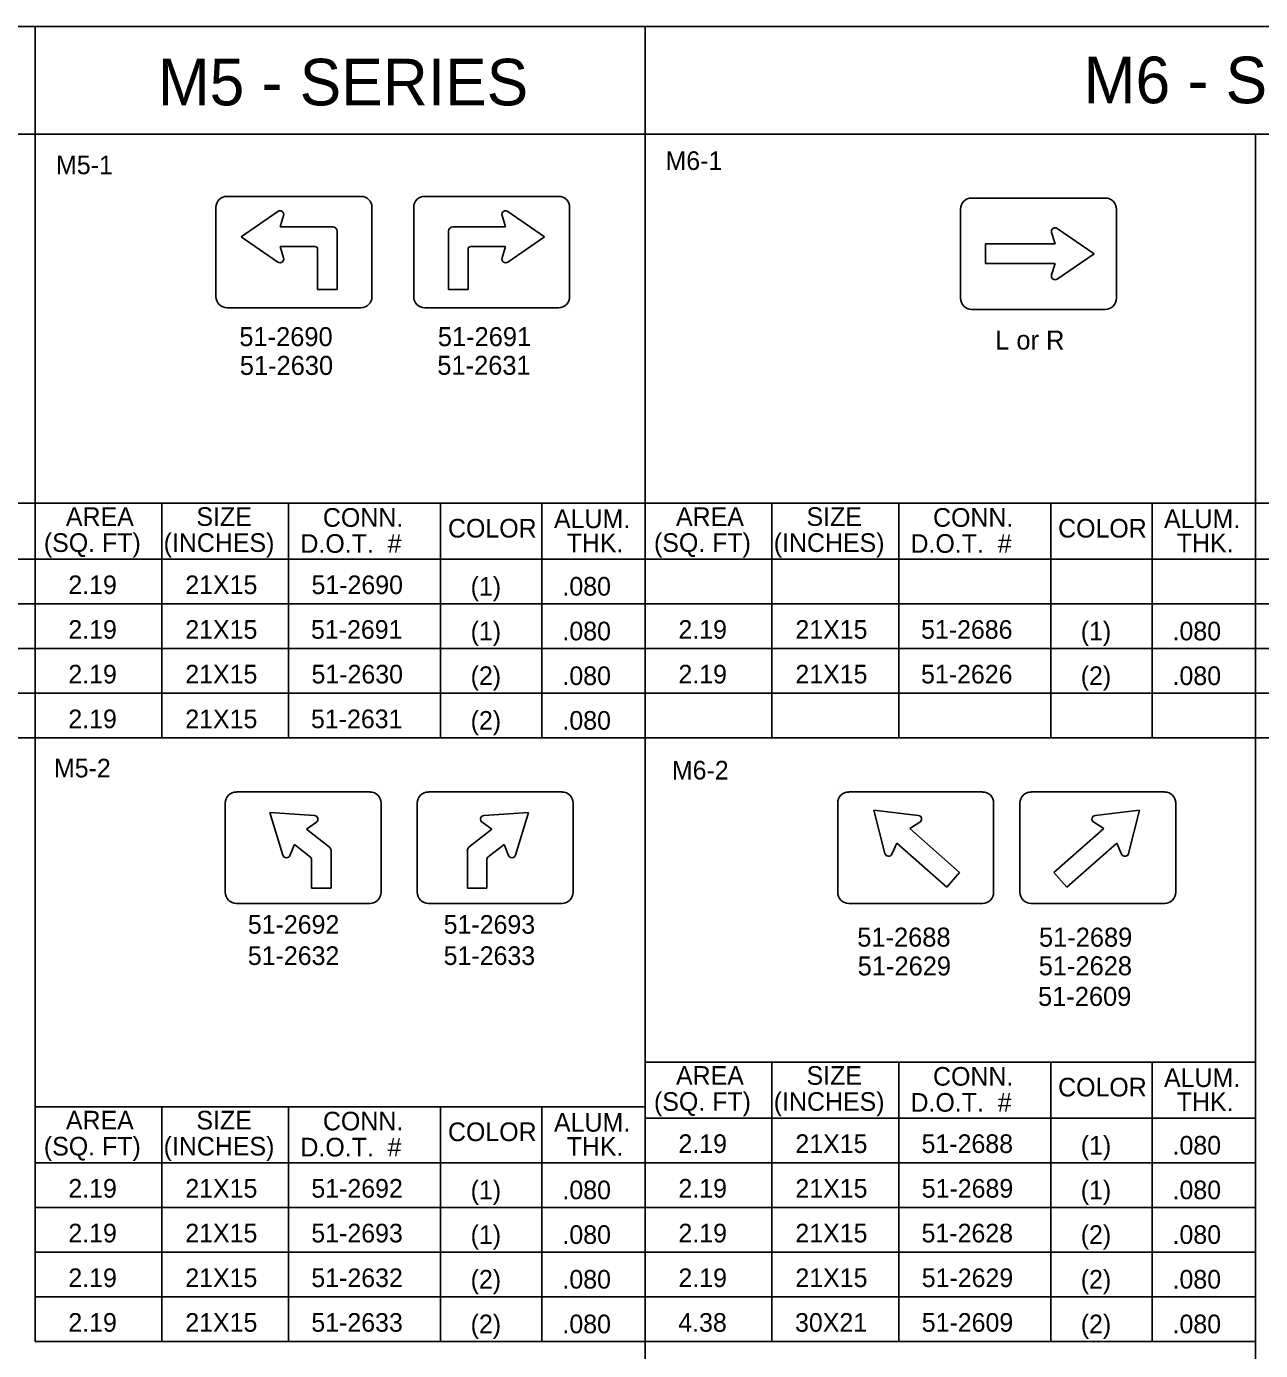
# Model space of a CAD drawing. Extents: x 0 to 2011, y -22 to 1183.
# Drawn here: x 527.3 to 739.2, y 163.9 to 391.3 of the extents above; entities that cross this region are included whole.
import ezdxf

# ---------------------------------------------------------------- set-up
doc = ezdxf.new("R2010")
doc.units = 0
for name, color, linetype in [('Default', 7, 'Continuous'), ('Level 1', 7, 'Continuous'), ('Level 2', 7, 'Continuous'), ('Level 5', 7, 'Continuous')]:
    doc.layers.add(name, color=color, linetype=linetype)

msp = doc.modelspace()

# ---------------------------------------------------------------- linework, layer by layer
at = {"layer": 'Default'}
msp.add_line((1262.03, 391.26), (5.05, 391.26), dxfattribs=at)
at = {"layer": 'Level 1'}
for p, q in [((584.69, 362.1), (561.74, 362.1)), ((595.69, 362.1), (618.64, 362.1)), ((712.51, 361.81), (689.57, 361.81)), ((559.83, 360.18), (559.83, 344.89)), ((564.13, 355.16), (570.46, 359.51)), ((570.46, 359.51), (570.46, 359.51)), ((586.6, 344.89), (586.6, 360.18)), ((593.78, 344.89), (593.78, 360.18)), ((609.92, 359.51), (609.92, 359.51)), ((616.25, 355.16), (609.92, 359.51)), ((620.55, 360.18), (620.55, 344.89)), ((687.65, 359.89), (687.65, 344.6)), ((714.43, 344.6), (714.43, 359.89)), ((571.43, 358.81), (570.84, 356.84)), ((608.95, 358.81), (609.54, 356.84)), ((564.13, 355.16), (564.13, 355.16)), ((570.46, 350.82), (564.13, 355.16)), ((570.84, 356.84), (579.91, 356.84)), ((580.62, 356.12), (580.62, 346.08)), ((599.76, 356.12), (599.76, 346.08)), ((609.54, 356.84), (600.47, 356.84)), ((609.92, 350.82), (616.25, 355.16)), ((616.25, 355.16), (616.25, 355.16)), ((703.3, 355.89), (703.89, 353.92)), ((710.6, 352.25), (704.27, 356.6)), ((576.8, 353.49), (570.84, 353.49)), ((570.84, 353.49), (571.43, 351.52)), ((577.28, 346.08), (577.28, 353.01)), ((603.1, 346.08), (603.1, 353.01)), ((603.58, 353.49), (609.54, 353.49)), ((609.54, 353.49), (608.95, 351.52)), ((703.89, 353.92), (691.96, 353.92)), ((691.96, 353.92), (691.96, 350.57)), ((691.96, 350.57), (703.89, 350.57)), ((703.89, 350.57), (703.3, 348.6)), ((704.27, 347.9), (710.6, 352.25)), ((710.6, 352.25), (710.6, 352.25)), ((710.6, 352.25), (710.6, 352.25)), ((580.62, 346.08), (577.28, 346.08)), ((580.62, 346.08), (580.62, 346.08)), ((599.76, 346.08), (599.76, 346.08)), ((599.76, 346.08), (603.1, 346.08)), ((561.74, 342.97), (584.69, 342.97)), ((618.64, 342.97), (595.69, 342.97)), ((689.57, 342.68), (712.51, 342.68)), ((586.28, 259.84), (563.33, 259.84)), ((596.29, 259.84), (619.24, 259.84)), ((668.48, 259.84), (691.43, 259.84)), ((722.72, 259.84), (699.77, 259.84)), ((561.42, 257.92), (561.42, 242.63)), ((588.19, 242.63), (588.19, 257.92)), ((594.38, 242.63), (594.38, 257.92)), ((621.15, 257.92), (621.15, 242.63)), ((666.57, 242.63), (666.57, 257.92)), ((693.34, 257.92), (693.34, 242.63)), ((697.86, 257.92), (697.86, 242.63)), ((724.63, 242.63), (724.63, 257.92)), ((569.07, 256.33), (569.07, 256.33)), ((569.07, 256.33), (569.07, 256.33)), ((569.07, 256.33), (571.33, 248.99)), ((576.73, 255.8), (569.07, 256.33)), ((575.37, 253.47), (577.06, 254.65)), ((607.2, 253.47), (605.52, 254.65)), ((605.84, 255.8), (613.5, 256.33)), ((613.5, 256.33), (611.25, 248.99)), ((613.5, 256.33), (613.5, 256.33)), ((613.5, 256.33), (613.5, 256.33)), ((672.79, 256.73), (672.79, 256.73)), ((674.68, 249.28), (672.79, 256.73)), ((672.79, 256.73), (672.79, 256.73)), ((672.79, 256.73), (680.41, 255.82)), ((680.68, 254.65), (678.94, 253.56)), ((710.52, 254.65), (712.26, 253.56)), ((718.41, 256.73), (710.78, 255.82)), ((716.52, 249.28), (718.41, 256.73)), ((718.41, 256.73), (718.41, 256.73)), ((718.41, 256.73), (718.41, 256.73)), ((579.32, 250.34), (575.37, 253.47)), ((603.26, 250.34), (607.2, 253.47)), ((678.94, 253.56), (687.51, 246.03)), ((712.26, 253.56), (703.68, 246.03)), ((572.53, 248.94), (573.29, 250.85)), ((573.29, 250.85), (576.06, 248.65)), ((609.28, 250.85), (606.52, 248.65)), ((610.04, 248.94), (609.28, 250.85)), ((676.73, 251.04), (675.87, 249.17)), ((685.31, 243.52), (676.73, 251.04)), ((705.89, 243.52), (714.47, 251.04)), ((714.47, 251.04), (715.32, 249.17)), ((576.24, 248.28), (576.24, 243.34)), ((579.59, 243.34), (579.59, 249.78)), ((602.99, 243.34), (602.99, 249.78)), ((606.33, 248.28), (606.33, 243.34)), ((687.51, 246.03), (685.31, 243.52)), ((703.68, 246.03), (705.89, 243.52)), ((576.24, 243.34), (576.24, 243.34)), ((576.24, 243.34), (579.59, 243.34)), ((606.33, 243.34), (602.99, 243.34)), ((606.33, 243.34), (606.33, 243.34)), ((563.33, 240.71), (586.28, 240.71)), ((619.24, 240.71), (596.29, 240.71)), ((691.43, 240.71), (668.48, 240.71)), ((699.77, 240.71), (722.72, 240.71))]:
    msp.add_line(p, q, dxfattribs=at)
for centre, radius, start, end in [((561.74, 360.18), 1.91, 90, 180), ((584.69, 360.18), 1.91, 0, 90), ((595.69, 360.18), 1.91, 90, 180), ((618.64, 360.18), 1.91, 360, 90), ((689.57, 359.9), 1.91, 90, 180), ((712.51, 359.9), 1.91, 0, 90), ((570.82, 358.99), 0.637, 343.3591, 124.4886), ((609.56, 358.99), 0.637, 55.5114, 196.6409), ((579.91, 356.12), 0.717, 360, 90), ((600.47, 356.12), 0.717, 90, 180), ((703.91, 356.07), 0.637, 55.5114, 196.6409), ((576.8, 353.01), 0.478, 0, 90), ((603.58, 353.01), 0.478, 90, 180), ((570.82, 351.34), 0.637, 235.5114, 16.6409), ((609.56, 351.34), 0.637, 163.3591, 304.4886), ((703.91, 348.42), 0.637, 163.3591, 304.4886), ((561.74, 344.89), 1.91, 180, 270), ((584.69, 344.89), 1.91, 270, 360), ((595.69, 344.89), 1.91, 180, 270), ((618.64, 344.89), 1.91, 270, 0), ((689.57, 344.6), 1.91, 180, 270), ((712.51, 344.6), 1.91, 270, 360), ((563.33, 257.92), 1.91, 90, 180), ((586.28, 257.92), 1.91, 0, 90), ((596.29, 257.92), 1.91, 90, 180), ((619.24, 257.92), 1.91, 360, 90), ((668.48, 257.92), 1.91, 90, 180), ((691.43, 257.92), 1.91, 360, 90), ((699.77, 257.92), 1.91, 90, 180), ((722.72, 257.92), 1.91, 0, 90), ((576.69, 255.17), 0.637, 304.9519, 86.0815), ((605.88, 255.17), 0.637, 93.9185, 235.0481), ((680.34, 255.19), 0.637, 302.1021, 83.2316), ((710.86, 255.19), 0.637, 96.7684, 237.8979), ((578.87, 249.78), 0.717, 0, 51.5927), ((603.7, 249.78), 0.717, 128.4073, 180), ((571.94, 249.18), 0.637, 197.1043, 338.2338), ((575.76, 248.28), 0.478, 0, 51.5932), ((606.81, 248.28), 0.478, 128.4068, 180), ((610.64, 249.18), 0.637, 201.7662, 342.8957), ((675.29, 249.44), 0.637, 194.2544, 335.3839), ((715.9, 249.44), 0.637, 204.6161, 345.7456), ((563.33, 242.63), 1.91, 180, 270), ((586.28, 242.63), 1.91, 270, 360), ((596.29, 242.63), 1.91, 180, 270), ((619.24, 242.63), 1.91, 270, 0), ((668.48, 242.63), 1.91, 180, 270), ((691.43, 242.63), 1.91, 270, 0), ((699.77, 242.63), 1.91, 180, 270), ((722.72, 242.63), 1.91, 270, 360)]:
    msp.add_arc(centre, radius, start, end, dxfattribs=at)
at = {"layer": 'Level 2'}
for p, q in [((586.6, 362.1), (586.6, 362.1)), ((593.78, 362.1), (593.78, 362.1)), ((714.43, 361.81), (714.43, 361.81)), ((559.83, 342.97), (559.83, 342.97)), ((620.55, 342.97), (620.55, 342.97)), ((687.65, 342.68), (687.65, 342.68)), ((424.05, 309.4), (528.79, 309.4)), ((528.79, 309.4), (633.54, 309.4)), ((550.54, 309.4), (550.54, 269.13)), ((572.29, 309.4), (572.29, 269.13)), ((598.39, 309.4), (598.39, 269.13)), ((615.79, 309.4), (615.79, 269.13)), ((633.54, 309.4), (738.29, 309.4)), ((655.29, 309.4), (655.29, 269.13)), ((677.04, 309.4), (677.04, 269.13)), ((703.14, 309.4), (703.14, 269.13)), ((720.54, 309.4), (720.54, 269.13)), ((738.29, 309.4), (843.04, 309.4)), ((424.05, 299.81), (528.79, 299.81)), ((528.79, 299.81), (633.54, 299.81)), ((633.54, 299.81), (738.29, 299.81)), ((738.29, 299.81), (843.04, 299.81)), ((424.05, 292.14), (528.79, 292.14)), ((528.79, 292.14), (633.54, 292.14)), ((633.54, 292.14), (738.29, 292.14)), ((738.29, 292.14), (843.04, 292.14)), ((424.05, 284.47), (528.79, 284.47)), ((528.79, 284.47), (633.54, 284.47)), ((633.54, 284.47), (738.29, 284.47)), ((738.29, 284.47), (843.04, 284.47)), ((424.05, 276.8), (528.79, 276.8)), ((528.79, 276.8), (633.54, 276.8)), ((633.54, 276.8), (738.29, 276.8)), ((738.29, 276.8), (843.04, 276.8)), ((588.19, 259.84), (588.19, 259.84)), ((594.38, 259.84), (594.38, 259.84)), ((666.57, 259.84), (666.57, 259.84)), ((724.63, 259.84), (724.63, 259.84)), ((561.42, 240.71), (561.42, 240.71)), ((621.15, 240.71), (621.15, 240.71)), ((693.34, 240.71), (693.34, 240.71)), ((697.86, 240.71), (697.86, 240.71)), ((633.54, 213.45), (738.29, 213.45)), ((655.29, 213.45), (655.29, 165.5)), ((677.04, 213.45), (677.04, 165.5)), ((703.14, 213.45), (703.14, 165.5)), ((720.54, 213.45), (720.54, 165.5)), ((528.79, 205.78), (633.54, 205.78)), ((550.54, 205.78), (550.54, 165.5)), ((572.29, 205.78), (572.29, 165.5)), ((598.39, 205.78), (598.39, 165.5)), ((615.79, 205.78), (615.79, 165.5)), ((633.54, 203.86), (738.29, 203.86)), ((528.79, 196.19), (633.54, 196.19)), ((633.54, 196.19), (738.29, 196.19)), ((528.79, 188.52), (633.54, 188.52)), ((633.54, 188.52), (738.29, 188.52)), ((528.79, 180.85), (633.54, 180.85)), ((633.54, 180.85), (738.29, 180.85)), ((528.79, 173.18), (633.54, 173.18)), ((633.54, 173.18), (738.29, 173.18))]:
    msp.add_line(p, q, dxfattribs=at)
for points in [[(528.79, 372.75), (424.05, 372.75), (424.05, 269.13), (528.79, 269.13)], [(633.54, 372.75), (528.79, 372.75), (528.79, 269.13), (633.54, 269.13)], [(738.29, 372.75), (633.54, 372.75), (633.54, 269.13), (738.29, 269.13)], [(843.04, 372.75), (738.29, 372.75), (738.29, 269.13), (843.04, 269.13)], [(633.54, 269.13), (528.79, 269.13), (528.79, 165.5), (633.54, 165.5)], [(738.29, 269.13), (633.54, 269.13), (633.54, 165.5), (738.29, 165.5)], [(738.29, 165.5), (633.54, 165.5), (633.54, 61.88), (738.29, 61.88)]]:
    msp.add_lwpolyline(points, close=True, dxfattribs=at)
for points in [[(674.86, 248.98), (674.83, 249)], [(716.34, 248.98), (716.37, 249)]]:
    msp.add_lwpolyline(points, dxfattribs=at)
at = {"layer": 'Level 5'}
for p, q in [((528.79, 391.26), (528.79, 165.5)), ((633.54, 391.26), (633.54, 61.88))]:
    msp.add_line(p, q, dxfattribs=at)

# ---------------------------------------------------------------- texts
at = {"layer": 'Level 1'}
for s, height, p in [('M5 - SERIES', 8, (549.83, 377.72)), ('M6 - SERIES', 8, (708.8, 378.08)), ('51-2690', 3.264, (563.84, 336.38)), ('51-2691', 3.264, (597.92, 336.38)), ('51-2630', 3.264, (563.92, 331.44)), ('51-2631', 3.264, (597.83, 331.46)), ('51-2688', 3.264, (669.93, 233.29)), ('51-2689', 3.264, (701.13, 233.28)), ('51-2629', 3.264, (670.01, 228.34)), ('51-2628', 3.264, (701.08, 228.37)), ('51-2609', 3.264, (700.97, 223.11))]:
    msp.add_text(s, height=height, dxfattribs=at).set_placement(p)
at = {"layer": 'Level 2'}
for s, height, p in [('M5-1', 3.2, (532.37, 365.9)), ('M6-1', 3.2, (637.01, 366.63)), ('L or R', 3.264, (693.61, 335.8)), ('AREA', 3.2, (534.06, 305.52)), ('SIZE', 3.2, (556.47, 305.52)), ('CONN.', 3.2, (578.19, 305.37)), ('ALUM.', 3.2, (617.86, 305.14)), ('AREA', 3.2, (638.81, 305.52)), ('SIZE', 3.2, (661.22, 305.52)), ('CONN.', 3.2, (682.94, 305.37)), ('ALUM.', 3.2, (722.6, 305.14)), ('COLOR', 3.2, (599.66, 303.52)), ('COLOR', 3.2, (704.41, 303.52)), ('(SQ. FT)', 3.2, (530.28, 301.05)), ('(INCHES)', 3.2, (550.84, 301.05)), ('D.O.T.  #', 3.2, (574.33, 300.9)), ('THK.', 3.2, (620.03, 301)), ('(SQ. FT)', 3.2, (635.03, 301.05)), ('(INCHES)', 3.2, (655.59, 301.05)), ('D.O.T.  #', 3.2, (679.07, 300.9)), ('THK.', 3.2, (724.78, 301)), ('M5-2', 3.2, (532.01, 262.34)), ('M6-2', 3.2, (638.1, 261.98)), ('51-2692', 3.2, (565.3, 235.5)), ('51-2693', 3.2, (598.92, 235.5)), ('51-2632', 3.2, (565.3, 230.14)), ('51-2633', 3.2, (598.92, 230.14)), ('AREA', 3.2, (638.81, 209.57)), ('SIZE', 3.2, (661.22, 209.57)), ('CONN.', 3.2, (682.94, 209.42)), ('ALUM.', 3.2, (722.6, 209.19)), ('COLOR', 3.2, (704.41, 207.57)), ('(SQ. FT)', 3.2, (635.03, 205.1)), ('(INCHES)', 3.2, (655.59, 205.1)), ('D.O.T.  #', 3.2, (679.07, 204.95)), ('THK.', 3.2, (724.78, 205.05)), ('AREA', 3.2, (534.06, 201.9)), ('SIZE', 3.2, (556.47, 201.9)), ('CONN.', 3.2, (578.19, 201.74)), ('ALUM.', 3.2, (617.86, 201.52)), ('COLOR', 3.2, (599.66, 199.9)), ('(SQ. FT)', 3.2, (530.28, 197.43)), ('(INCHES)', 3.2, (550.84, 197.43)), ('D.O.T.  #', 3.2, (574.33, 197.27)), ('THK.', 3.2, (620.03, 197.38))]:
    msp.add_text(s, height=height, dxfattribs=at).set_placement(p)
at = {"layer": 'Level 5'}
for s, p in [(' 2.19', (533.29, 293.81)), ('21X15', (554.56, 293.81)), ('51-2690', (576.23, 293.81)), ('(1)', (603.55, 293.55)), ('.080', (619.31, 293.55)), (' 2.19', (533.29, 286.14)), ('21X15', (554.56, 286.14)), ('51-2691', (576.14, 286.14)), ('(1)', (603.55, 285.87)), ('.080', (619.31, 285.87)), (' 2.19', (638.04, 286.14)), ('21X15', (659.31, 286.14)), ('51-2686', (680.88, 286.14)), ('(1)', (708.3, 285.87)), ('.080', (724.06, 285.87)), (' 2.19', (533.29, 278.47)), ('21X15', (554.56, 278.47)), ('51-2630', (576.23, 278.47)), ('(2)', (603.55, 278.2)), ('.080', (619.31, 278.2)), (' 2.19', (638.04, 278.47)), ('21X15', (659.31, 278.47)), ('51-2626', (680.88, 278.47)), ('(2)', (708.3, 278.2)), ('.080', (724.06, 278.2)), (' 2.19', (533.29, 270.79)), ('21X15', (554.56, 270.79)), ('51-2631', (576.14, 270.79)), ('(2)', (603.55, 270.53)), ('.080', (619.31, 270.53)), (' 2.19', (638.04, 197.86)), ('21X15', (659.31, 197.86)), ('51-2688', (680.97, 197.86)), ('(1)', (708.3, 197.59)), ('.080', (724.06, 197.59)), (' 2.19', (533.29, 190.19)), ('21X15', (554.56, 190.19)), ('51-2692', (576.2, 190.19)), ('(1)', (603.55, 189.92)), (' 2.19', (638.04, 190.19)), ('21X15', (659.31, 190.19)), ('51-2689', (681, 190.19)), ('(1)', (708.3, 189.92)), ('.080', (619.31, 189.92)), ('.080', (724.06, 189.92)), (' 2.19', (533.29, 182.51)), ('21X15', (554.56, 182.51)), ('51-2693', (576.2, 182.51)), ('(1)', (603.55, 182.25)), ('.080', (619.31, 182.25)), (' 2.19', (638.04, 182.51)), ('21X15', (659.31, 182.51)), ('51-2628', (680.97, 182.51)), ('(2)', (708.3, 182.25)), ('.080', (724.06, 182.25)), (' 2.19', (533.29, 174.84)), ('21X15', (554.56, 174.84)), ('51-2632', (576.2, 174.84)), ('(2)', (603.55, 174.58)), ('.080', (619.31, 174.58)), (' 2.19', (638.04, 174.84)), ('21X15', (659.31, 174.84)), ('51-2629', (681, 174.84)), ('(2)', (708.3, 174.58)), ('.080', (724.06, 174.58)), (' 2.19', (533.29, 167.17)), ('21X15', (554.56, 167.17)), ('51-2633', (576.2, 167.17)), ('(2)', (603.55, 166.91)), ('.080', (619.31, 166.91)), (' 4.38', (638.01, 167.17)), ('30X21', (659.25, 167.17)), ('51-2609', (681, 167.17)), ('(2)', (708.3, 166.91)), ('.080', (724.06, 166.91))]:
    msp.add_text(s, height=3.2, dxfattribs=at).set_placement(p)

doc.saveas('drawing.dxf')
